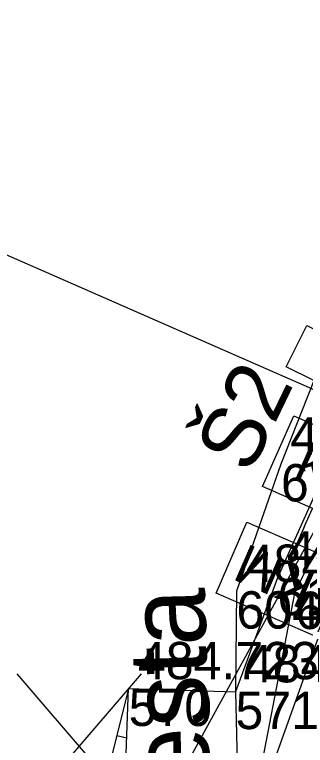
# Model space of a CAD drawing. Extents: x -874038 to -859694, y -1059487 to -1049069.
# Drawn here: x -866901.73 to -866892.41, y -1050795.92 to -1050772.45 of the extents above; entities that cross this region are included whole.
import ezdxf

# ---------------------------------------------------------------- set-up
doc = ezdxf.new("R2010")
doc.units = 0
for name, color, linetype in [('Vrstva 1', 7, 'Continuous'), ('Vrstva 33', 7, 'Continuous'), ('Vrstva 4', 7, 'Continuous'), ('Vrstva 43', 7, 'Continuous'), ('Vrstva 44', 7, 'Continuous'), ('Vrstva 48', 7, 'Continuous'), ('Vrstva 49', 7, 'Continuous'), ('Vrstva 51', 7, 'Continuous'), ('Vrstva 60', 7, 'Continuous'), ('Vrstva 61', 7, 'Continuous'), ('Vrstva 7', 7, 'Continuous')]:
    doc.layers.add(name, color=color, linetype=linetype)

msp = doc.modelspace()

# ---------------------------------------------------------------- linework, layer by layer
at = {"layer": 'Vrstva 1'}
msp.add_line((-866938.682, -1050764.049), (-866887.686, -1050786.453), dxfattribs=at)
at = {"layer": 'Vrstva 33'}
msp.add_lwpolyline([(-866893.024, -1050783.766), (-866892.363, -1050782.432), (-866888.753, -1050784.221), (-866889.414, -1050785.555)], close=True, dxfattribs=at)
at = {"layer": 'Vrstva 4'}
for p, q in [((-866901.668, -1050793.623), (-866898.668, -1050797.123)), ((-866900.668, -1050797.123), (-866897.668, -1050793.623))]:
    msp.add_line(p, q, dxfattribs=at)
for points in [[(-866892.733, -1050790.985), (-866891.263, -1050788.067), (-866879.491, -1050760.405), (-866874.327, -1050747.254)], [(-866891.558, -1050791.236), (-866894.209, -1050798.657), (-866892.733, -1050790.985)]]:
    msp.add_lwpolyline(points, dxfattribs=at)
at = {"layer": 'Vrstva 44'}
msp.add_lwpolyline([(-866912.752, -1050826.723), (-866890.904, -1050786.8), (-866874.15, -1050746.784), (-866858.678, -1050710.211), (-866845.122, -1050668.894)], dxfattribs=at)
at = {"layer": 'Vrstva 48'}
msp.add_line((-866898.139, -1050795.696), (-866898.456, -1050795.618), dxfattribs=at)
at = {"layer": 'Vrstva 49'}
for points in [[(-866873.576, -1050737.504), (-866877.343, -1050746.621), (-866882.324, -1050759.317), (-866893.193, -1050786.886), (-866894.623, -1050790.972), (-866894.652, -1050794.2)], [(-866880.912, -1050759.876), (-866892.027, -1050787.7), (-866893.306, -1050790.542), (-866894.652, -1050794.2)], [(-866898.079, -1050794.1), (-866899.618, -1050800.297), (-866904.374, -1050808.594)]]:
    msp.add_lwpolyline(points, dxfattribs=at)
at = {"layer": 'Vrstva 51'}
for p, q in [((-866898.565, -1050806.967), (-866898.079, -1050794.1)), ((-866898.079, -1050794.1), (-866894.652, -1050794.2)), ((-866894.652, -1050794.2), (-866894.525, -1050799.306))]:
    msp.add_line(p, q, dxfattribs=at)
at = {"layer": 'Vrstva 60'}
for p, q in [((-866893.193, -1050786.886), (-866893.193, -1050786.886)), ((-866892.436, -1050788.879), (-866892.436, -1050788.879)), ((-866893.306, -1050790.542), (-866893.306, -1050790.542)), ((-866894.623, -1050790.972), (-866894.623, -1050790.972)), ((-866892.733, -1050790.985), (-866892.733, -1050790.985)), ((-866898.079, -1050794.1), (-866898.079, -1050794.1)), ((-866894.652, -1050794.2), (-866894.652, -1050794.2))]:
    msp.add_line(p, q, dxfattribs=at)
at = {"layer": 'Vrstva 7'}
for q in [(-866892.186, -1050788.309), (-866892.684, -1050789.45)]:
    msp.add_line((-866892.436, -1050788.879), q, dxfattribs=at)
for points in [[(-866893.781, -1050787.608), (-866892.782, -1050785.335), (-866889.589, -1050786.737), (-866890.587, -1050789.01)], [(-866891.087, -1050790.145), (-866892.076, -1050792.422), (-866895.275, -1050791.032), (-866894.286, -1050788.754)]]:
    msp.add_lwpolyline(points, close=True, dxfattribs=at)

# ---------------------------------------------------------------- texts
at = {"layer": 'Vrstva 43'}
msp.add_text('Š2', height=2, rotation=64.296, dxfattribs=at).set_placement((-866894.186, -1050787.252))
at = {"layer": 'Vrstva 51'}
msp.add_text('cesta', height=2.5, rotation=91.4248, dxfattribs=at).set_placement((-866895.436, -1050798.841))
at = {"layer": 'Vrstva 60'}
for s, p in [('610', (-866893.193, -1050788.086)), ('612', (-866893.306, -1050791.742)), ('604', (-866894.623, -1050792.172)), ('611', (-866892.733, -1050792.185)), ('570', (-866898.079, -1050795.3)), ('571', (-866894.652, -1050795.4))]:
    msp.add_text(s, height=1.2, dxfattribs=at).set_placement(p)
at = {"layer": 'Vrstva 61'}
for s, p in [('484.686', (-866892.893, -1050786.586)), ('483.852', (-866893.006, -1050790.242)), ('484.707', (-866894.323, -1050790.672)), ('484.723', (-866897.779, -1050793.8)), ('484.669', (-866894.352, -1050793.9))]:
    msp.add_text(s, height=1.2, dxfattribs=at).set_placement(p)
at = {"layer": 'Vrstva 7'}
for height, rotation, p in [(1.2469, 336.2953, (-866892.868, -1050787.333)), (1.2468, 156.5112, (-866891.998, -1050790.423))]:
    msp.add_text('KM', height=height, rotation=rotation, dxfattribs=at).set_placement(p)

doc.saveas('drawing.dxf')
